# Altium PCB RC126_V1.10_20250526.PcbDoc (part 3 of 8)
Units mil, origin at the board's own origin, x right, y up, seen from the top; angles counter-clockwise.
Board outline 6299.62 x 3544.12 mil, 4 copper layers (Top, GND, Power, Bottom), stack 35.4 mil thick; 509 components, 417 nets, 1867 pads, 2150 vias.
Unrouted connection lines stored in the file: 1451.
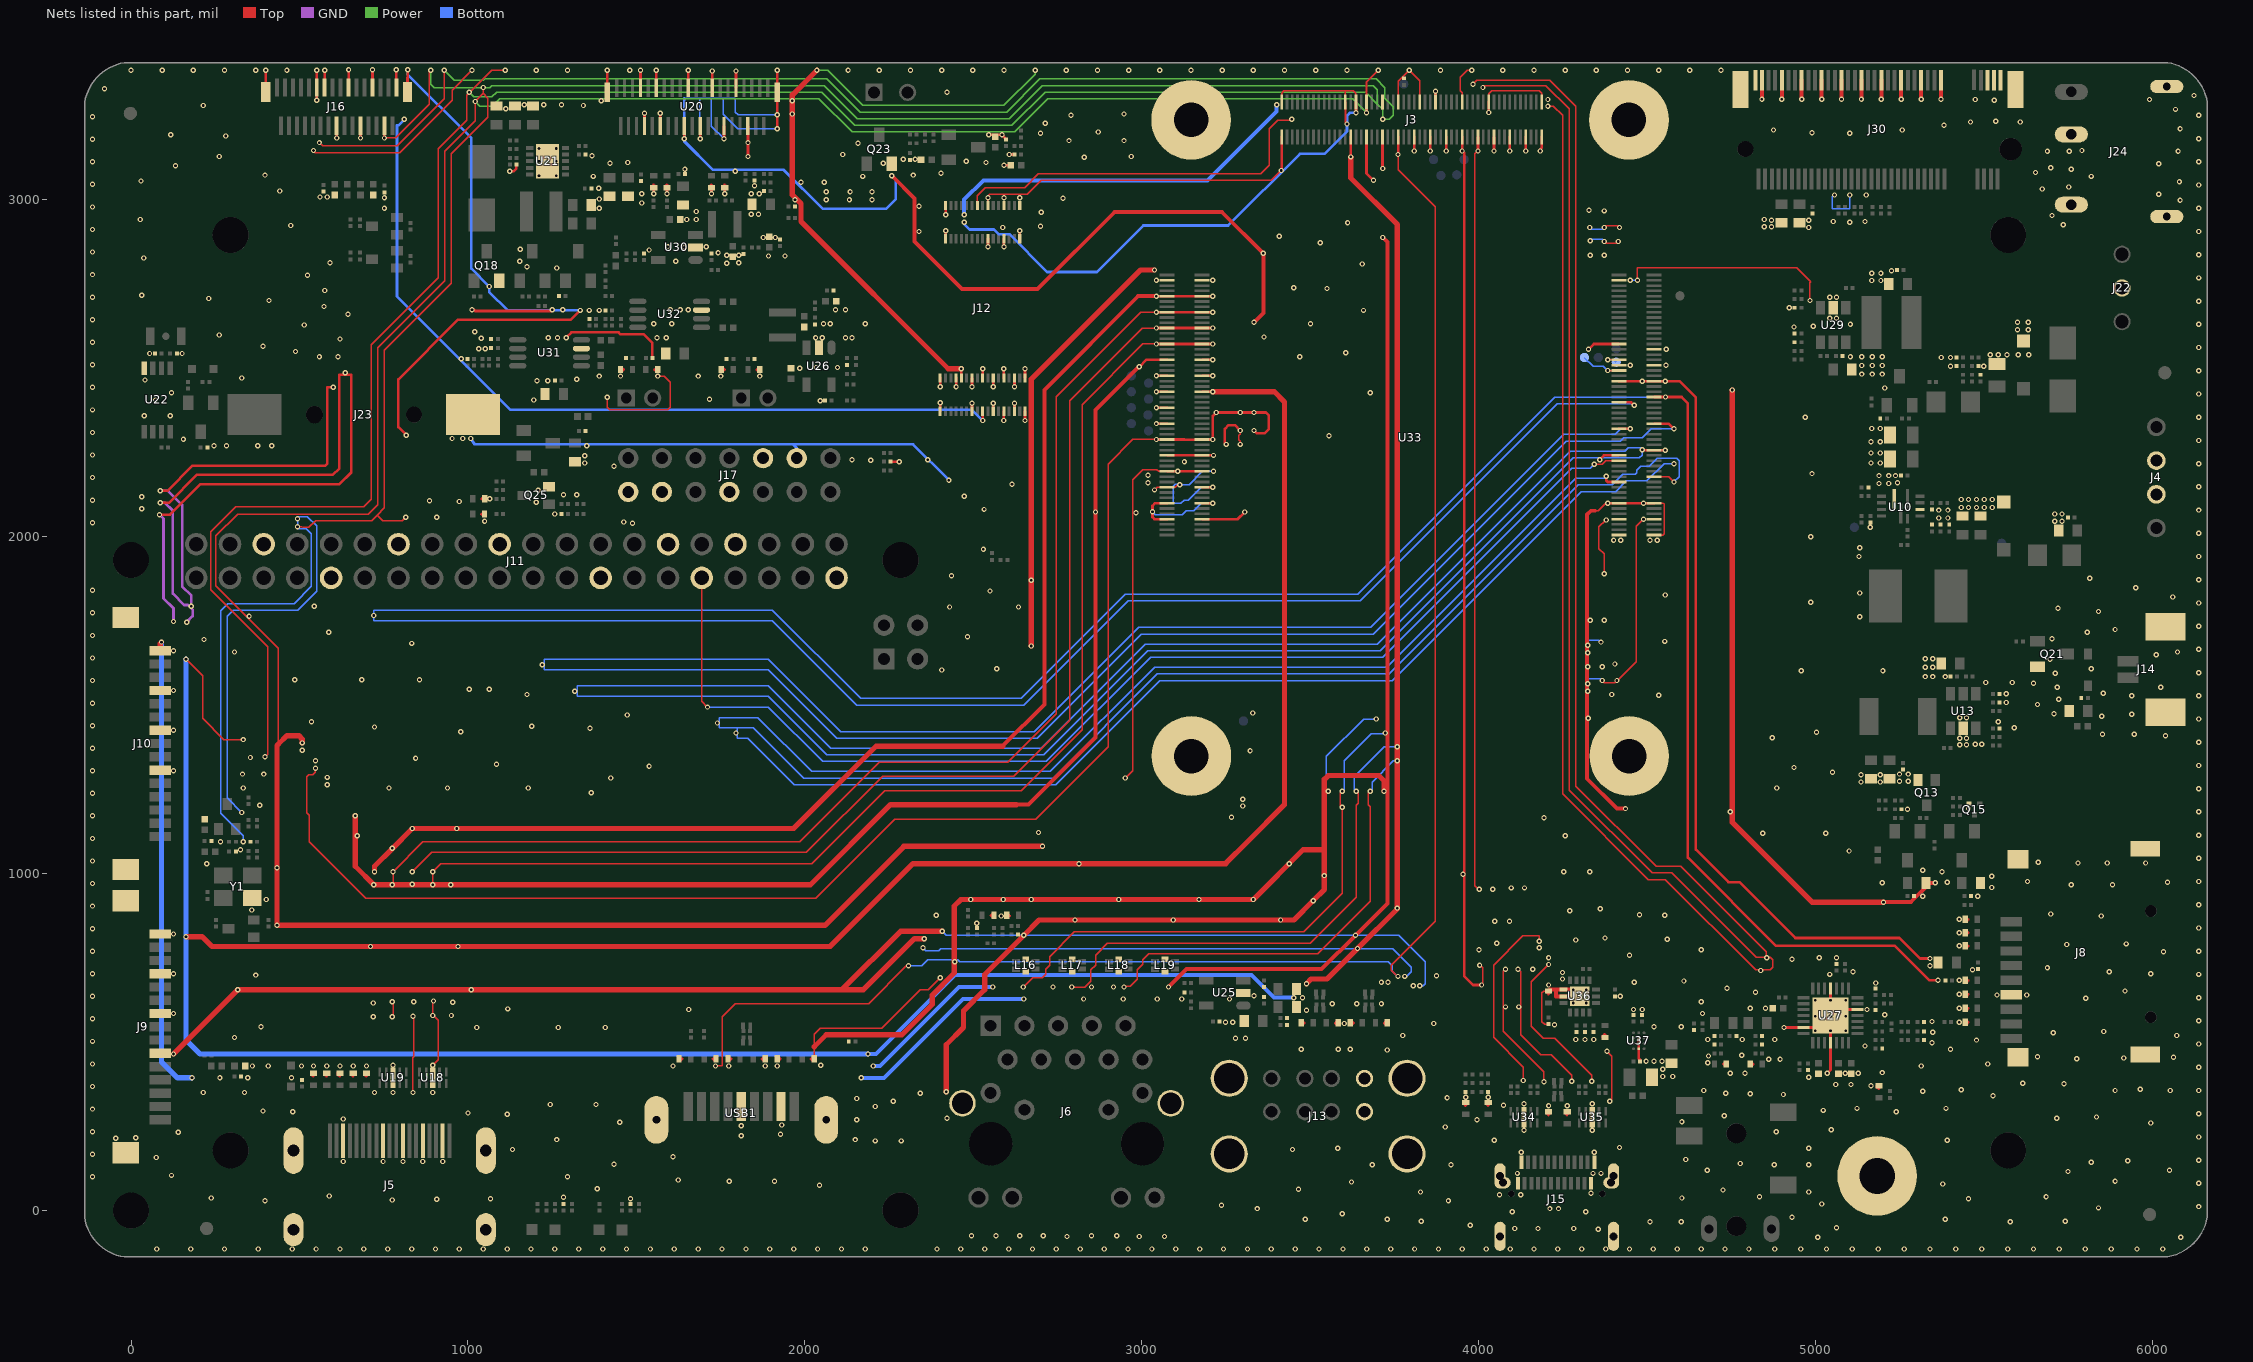
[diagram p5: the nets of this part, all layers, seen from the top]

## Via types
v1: diameter 15.75, hole 7.87, Top to Bottom, 2047 vias
v2: diameter 19.68, hole 11.81, Top to Bottom, 103 vias

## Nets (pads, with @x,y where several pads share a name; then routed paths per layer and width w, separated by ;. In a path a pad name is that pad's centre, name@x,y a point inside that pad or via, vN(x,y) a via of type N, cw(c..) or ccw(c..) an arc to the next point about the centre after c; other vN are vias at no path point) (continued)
GND: C1.2 C78.2 C79.2 C83.2 C84.2 C89.2 C90.2 C106.2 C107.2 C144.2 C146.2 C148.2 C150.2 C151.2 C153.2 C154.2 C156.2 C157.2 C158.2 C159.2 C161.1 C162.2 C163.2 C164.2 C167.2 C168.2 C169.1 C170.2 C171.2 C172.2 C174.2 C175.2 C176.2 C177.2 C178.2 C179.2 C180.1 C182.2 C183.2 C184.2 C185.2 C186.2 C187.1 C188.2 C189.1 C190.2 C191.2 C192.2 C193.2 C194.2 C195.2 C196.2 C197.2 C198.2 C199.2 C200.2 C202.2 C203.2 C206.2 C207.2 C208.2 C209.2 C211.2 C212.2 C213.2 C214.2 C215.2 C216.2 C218.2 C219.2 C220.2 C223.2 C224.2 C225.2 C226.2 C227.2 C229.2 C230.2 C231.2 C232.2 C233.2 C234.2 C235.2 C236.2 C237.2 C238.2 C239.2 C240.2 C241.2 C243.2 C244.2 C245.2 C246.2 C255.2 C256.2 C257.2 C258.2 C269.2 C270.2 C271.2 C272.2 C273.2 C274.2 C277.2 C279.2 C280.2 C281.2 C282.2 C283.1 C284.1 C285.2 C287.2 C288.2 C290.1 C291.1 C292.2 C294.2 C295.2 C297.2 C298.2 D1.1 D2.2 D3.2 D5.1 D7.2 D9.2 D10.2 D11.2 D12.2 D14.2 D15.2 D16.2 D17.1 D18.1 D19.1 D20.1 D21.1 D22.1 D23.1 D25.2 D26.2 D27.2 D28.2 D31.2 D32.2 D33.1 D34.1 D35.1 D36.1 D37.1 D38.1 D39.1 D40.1 D41.1 D42.1 D43.1 D44.1 D45.1 D46.1 D47.1 D48.1 D49.1 D50.1 D51.1 D52.1 HOLE2.1 J3.1 J3.2 J3.8 J3.14 J3.20 J3.21 J3.26 J3.31 J3.32 J3.38 J3.41 J3.44 J3.47 J3.50 J3.55 J3.56 J3.61 J3.62 J3.67 J3.68 J3.71 J3.74 J3.75 J3.99 J3.100 J4.2 J4.3 J5.2 J5.5 J5.8 J5.11 J5.17 J5.20 J5.21 J5.22 J5.23 J6.19 J6.20 J8.6 J8.10 J8.11 J8.12 J8.13 J9.6 J9.9 J9.12 J9.15 J9.16 J9.17 J10.6 J10.9 J10.12 J10.15 J10.16 J10.17 J11.6 J11.9 J11.14 J11.20 J11.25 J11.30 J11.34 J11.39 J12.1 J12.3 J12.5 J12.7 J12.9 J12.11 J12.13 J12.14 J12.17 J12.18 J12.24 J12.26 J12.28 J12.30 J12.32 J12.34 J12.35 J12.38 J12.41 J12.43 J12.49 J12.50 J12.58 J12.61 J12.64 J13.4 J13.8 J13.9 J13.10 J13.11 J13.12 J14.3 J14.4 J15.A1 J15.A12 J15.B1 J15.B12 J15.E1 J15.E2 J15.E3 J15.E4 J15.E5 J15.E6 J16.1 J16.4 J16.7 J16.10 J16.13 J16.16 J16.19 J16.21 J16.32 J16.33 J17.1 J17.3 J17.7 J17.10 J17.12 J22.2 J23.2 J24.2 J24.3 J24.4 J24.5 J30.1 J30.3 J30.9 J30.15 J30.21 J30.27 J30.33 J30.39 J30.45 J30.51 J30.57 J30.71 J30.73 J30.75 J30.G1 J30.G2 L16.5 L16.6 L17.5 L17.6 L18.5 L18.6 L19.5 L19.6 Q13.2 Q15.2 Q18.2 Q21.2 Q23.2 Q25.2 R4.2 R6.1 R27.1 R72.2 R177.1 R179.1 R201.1 R202.2 R205.2 R210.2 R217.2 R223.2 R226.2 R236.1 R239.1 R243.1 R244.2 R245.2 R251.2 R253.2 R280.2 R281.2 R286.1 R290.2 R298.1 R315.2 R316.2 R317.2 R318.2 R319.2 R330.2 R332.2 R333.2 R340.2 R341.2 R353.2 R354.2 R355.2 R359.2 U10.2 U10.10 U13.2 U18.3 U18.8 U19.3 U19.8 U20.6 U20.9 U20.12 U20.15 U20.18 U20.21 U20.22 U20.28 U20.29 U20.32 U20.33 U20.40 U20.41 U21.11 U22.4 U25.2 U26.2 U27.4 U27.13 U27.18 U27.26 U27.29 U29.2 U30.2 U31.7 U32.7 U33.1 U33.2 U33.7 U33.8 U33.13 U33.14 U33.22 U33.23 U33.32 U33.33 U33.42 U33.43 U33.52 U33.53 U33.59 U33.60 U33.65 U33.66 U33.71 U33.74 U33.98 U33.107 U33.108 U33.113 U33.114 U33.119 U33.120 U33.125 U33.126 U33.131 U33.132 U33.137 U33.138 U33.144 U33.150 U33.155 U33.156 U33.161 U33.162 U33.167 U33.168 U33.173 U33.174 U33.179 U33.180 U33.185 U33.186 U33.191 U33.192 U33.197 U33.198 U33.201 U33.202 U33.203 U33.204 U34.3 U34.8 U35.3 U35.8 U36.8 U36.9 U36.15 U37.A2 U37.B2 U37.C2 USB1.4 USB1.7 USB1.10 USB1.11 Y1.2 | length 175701.2
  Top w3.94: v1(163.39,1635.83) 212.6,1586.61 212.6,1460.63 275.59,1397.64 v1(332.68,1397.64) ; v1(397.64,1346.46) 405.51,1354.33 405.51,1673.23 236.22,1842.52 236.22,2013.78 311.02,2088.58 690.94,2088.58 712.6,2110.24 712.6,2568.9 911.42,2767.72 911.42,3151.57 996.06,3236.22 996.06,3309.06 1070.87,3383.86 v1(1110.24,3383.86) ; 437.01,1383.86 437.01,1669.29 251.97,1854.33 251.97,2001.97 316.93,2066.93 704.05,2066.93 732.28,2095.16 732.28,2561.02 931.1,2759.84 931.1,3143.7 1021.65,3234.25 v1(1021.65,3291.34) 1045.28,3314.96 ; v1(494.09,2029.53) 506.99,2029.53 508.96,2027.56 527.99,2027.56 547.68,2047.24 713.89,2047.24 730.64,2063.99 ; v1(541.34,3145.67) 547.24,3139.76 797.24,3139.76 952.76,3295.28 952.76,3324.8 v1(1011.81,3383.86) ; v1(547.24,1312.99) 547.24,1301.18 539.37,1293.31 527.56,1293.31 521.65,1287.4 521.65,1181.1 529.53,1173.23 529.53,1094.49 696.85,927.17 2031.5,927.17 2265.75,1161.42 2685.04,1161.42 2899.61,1375.98 2899.61,2214.57 2973.23,2288.19 v1(3042.91,2288.19) v1@3043.31,2288.19 ; v1(559.06,3169.29) 568.9,3159.45 789.37,3159.45 929.13,3299.21 v1(929.13,3383.86) ; v1(751.97,3183.07) 785.43,3183.07 884.84,3282.48 884.84,3383.86 v1(889.76,3383.86) ; v1(775.59,574.8) 777.56,576.77 777.56,618.11 v1(775.59,620.08) ; v1@777.56,966.54 v1(777.56,1005.91) 866.14,1094.49 1984.25,1094.49 2220.47,1330.71 2602.36,1330.71 2746.06,1474.41 2746.06,2415.35 2996.85,2666.14 v1(3042.91,2666.14) ; v1(814.96,2057.09) 805.12,2047.24 747.38,2047.24 730.64,2063.99 ; v1(834.65,1005.91) 891.73,1062.99 2003.94,1062.99 2230.32,1289.37 2620.08,1289.37 2785.43,1454.72 2785.43,2403.54 3000.79,2618.9 v1(3042.91,2618.9) ; v1(836.61,350.39) 836.61,454.72 838.58,454.72 838.58,574.8 v1(836.61,576.77) ; v1(895.67,431.1) 911.42,446.85 911.42,564.96 895.67,580.71 895.67,622.05 v1(897.64,622.05) ; v1(895.67,966.54) v1(895.67,1005.91) 919.29,1029.53 2019.68,1029.53 2236.22,1246.06 2641.73,1246.06 2822.83,1427.17 2822.83,2391.73 3002.76,2571.65 v1(3042.91,2571.65) ; v1(1045.28,3332.68) 1045.28,3314.96 ; v1(1413.39,2413.39) 1413.39,2383.86 1421.26,2375.98 1592.52,2375.98 1600.39,2383.86 1600.39,2458.66 1582.68,2476.38 v1(1562.99,2476.38) ; v1(1734.25,429.13) 1753.94,429.13 1753.94,574.8 1793.31,614.17 2188.98,614.17 2301.18,726.38 v1(2307.09,726.38) ; D40.1@2027.56,450.79 2027.56,486.22 2027.56,523.62 2045.28,541.34 2228.35,541.34 2342.52,655.51 2366.14,655.51 v1(2401.57,690.94) ; J12.43@2511.42,2982.28 2511.42,3011.81 2535.04,3035.43 2651.57,3035.43 2692.91,3076.77 3352.36,3076.77 3377.95,3102.36 3377.95,3210.63 3403.54,3236.22 3442.91,3236.22 3448.82,3236.22 v1(3444.88,3238.19) ; J12.41@2542.91,2982.28 2542.91,3009.84 2548.82,3015.75 2659.45,3015.75 2700.79,3057.09 3383.86,3057.09 v1(3413.39,3086.61) ; v1(2647.64,663.39) 2675.2,690.94 2704.72,690.94 2714.57,700.79 2714.57,716.54 2726.38,728.35 2726.38,753.94 2799.21,826.77 3480.32,826.77 3594.49,940.94 v1(3594.49,1196.85) 3588.58,1202.76 3588.58,1238.19 v1(3594.49,1244.09) ; v1(2791.34,663.39) 2830.71,663.39 2848.43,681.1 2848.43,714.57 2862.2,728.35 2862.2,757.87 2897.64,793.31 3500,793.31 3635.83,929.13 3635.83,1202.76 3641.73,1208.66 3641.73,1238.19 v1(3635.83,1244.09) ; v1(2946.85,663.39) 2948.82,665.35 2964.57,665.35 2986.22,687.01 2986.22,714.57 3001.97,730.32 3001.97,744.09 3019.68,761.81 3521.65,761.81 3677.17,917.32 3677.17,1198.82 3671.26,1204.72 3671.26,1238.19 v1(3677.17,1244.09) ; v1(2950.79,1283.46) 2972.44,1305.12 2972.44,2169.29 3001.97,2198.82 3044.09,2198.82 3049.21,2193.7 U33.126@3074.8,2193.7 ; v1(3037.4,2138.58) 3045.28,2146.46 U33.120@3074.8,2146.46 3098.43,2146.46 3106.3,2154.33 v1(3112.2,2154.33) ; v1@3208.27,2099.21 v1(3210.24,2099.21) ; v1(3291.34,2273.62) 3291.34,2283.46 3287.4,2287.4 3287.4,2300.1 3291.34,2304.03 v1(3291.34,2314.96) ; J3.100@3414.57,3181.9 J3.100@3414.57,3185.83 ; J3.99@3414.57,3289.77 3414.57,3302 3414.57,3316.14 3421.26,3322.83 3603.54,3322.83 ; J3.75@3603.55,3289 J3.75@3603.55,3289.77 3603.54,3322.83 ; J3.74@3619.3,3178.4 J3.74@3619.3,3185.83 ; J3.71@3635.04,3288.2 J3.71@3635.04,3289.77 3635.04,3314.96 3627.17,3322.83 3603.54,3322.83 ; J3.68@3666.54,3176.6 J3.68@3666.54,3185.83 ; J3.67@3666.54,3289.2 J3.67@3666.54,3289.77 ; J3.62@3713.78,3179.6 J3.62@3713.78,3185.83 ; v1(3759.84,694.88) 3757.87,694.88 3740.16,712.6 3740.16,728.35 3870.08,858.27 3870.08,2978.35 3759.84,3088.58 v1(3759.84,3133.86) ; J3.55@3761.02,3290.3 3761.02,3351.57 v1(3793.31,3383.86) 3824.02,3353.15 3824.02,3304.6 J3.47@3824.02,3289.77 ; J3.56@3761.03,3182.4 J3.56@3761.03,3185.83 ; J3.55@3761.03,3289.77 J3.55@3761.03,3290.3 ; J3.50@3808.27,3179.3 J3.50@3808.27,3185.83 ; J3.44@3855.52,3179.8 J3.44@3855.52,3185.83 ; J3.41@3871.26,3289.77 J3.41@3871.26,3299 ; J3.38@3902.76,3178.1 J3.38@3902.76,3185.83 ; J3.32@3950,3178.6 J3.32@3950,3185.83 ; v1(3978.35,3383.86) 3964.96,3383.86 3944.09,3362.99 3944.09,3323.62 3950,3317.72 J3.31@3950,3299.8 ; v1(3982.28,3342.52) 3994.09,3354.33 4210.63,3354.33 4287.4,3277.56 4287.4,1259.84 4525.59,1021.65 4598.43,1021.65 4852.36,767.72 v1@4852.36,751.97 ; v1(3997.24,3144.49) 3988.19,3135.43 3988.19,964.57 3998.03,954.72 4000,954.72 v1(4001.18,953.54) ; J3.26@3997.25,3179.3 J3.26@3997.25,3185.83 ; v1(4001.97,728.35) 4003.94,728.35 4011.81,720.47 4011.81,673.23 v1(4007.87,669.29) ; v1(4011.81,3332.68) 4017.72,3338.58 4198.82,3338.58 4267.72,3269.69 4267.72,1248.03 4513.78,1001.97 4572.83,1001.97 4822.83,751.97 v1@4852.36,751.97 ; J3.21@4028.74,3279.6 J3.21@4028.74,3289.77 4028.74,3314.17 4037.4,3322.83 4179.13,3322.83 4186.22,3315.75 4186.22,3298.5 J3.1@4186.22,3289.77 ; J3.20@4044.49,3178 J3.20@4044.49,3185.83 ; v1(4078.74,716.54) 4072.83,710.63 4072.83,531.5 4192.91,411.42 v1(4192.91,381.89) ; J3.14@4091.74,3179.6 J3.14@4091.74,3185.83 ; v1(4116.14,716.54) 4124.02,708.66 4124.02,521.65 4183.07,462.6 4214.57,462.6 4275.59,401.57 v1(4275.59,383.86) ; v1(4131.89,385.83) 4131.89,425.2 4043.31,513.78 4043.31,728.35 4129.92,814.96 4179.13,814.96 v1(4179.13,799.21) ; J3.8@4138.98,3176.9 J3.8@4138.98,3185.83 ; v1(4204.72,3277.56) 4220.47,3277.56 4248.03,3250 4248.03,1236.22 4501.97,982.28 4553.15,982.28 4820.87,714.57 4864.17,714.57 4872.05,722.44 4872.05,744.09 4864.17,751.97 v1@4852.36,751.97 ; C257.2@4206.69,553.15 4194.88,553.15 4187.01,561.02 4187.01,645.67 4192.91,651.57 D47.1@4206.69,651.57 ; v1(4206.69,730.32) 4155.51,679.13 4155.51,547.24 4190.94,511.81 4224.41,511.81 4334.65,401.57 v1(4334.65,383.86) ; 4344.49,2076.77 4354.33,2076.77 4376.77,2099.21 v1(4381.89,2099.21) ; v1(4366.14,1572.83) 4372.05,1566.93 4403.54,1566.93 v1(4409.45,1572.83) 4411.42,1574.8 4413.39,1574.8 4466.54,1627.95 4466.54,2030.32 v1(4488.19,2051.97) ; v1(4372.05,1889.76) 4372.05,1948.82 4356.3,1964.57 4356.3,2029.53 4375.98,2049.21 v1(4377.95,2049.21) ; v1(4372.05,2875.98) 4377.95,2870.08 4407.48,2870.08 v1(4413.39,2875.98) ; v1(4372.05,2917.32) 4377.95,2923.23 4411.42,2923.23 v1(4417.32,2917.32) ; v1(4379.92,472.44) 4393.7,458.66 4393.7,330.71 v1(4387.8,324.8) ; v1(4470.47,2760.63) 4470.47,2797.24 4942.91,2797.24 4984.25,2755.91 4982.28,2753.94 v1(4982.28,2700.79) ; U33.1@4520.08,2004.72 4546.06,2004.72 4549.21,2007.87 4549.21,2097.24 4547.24,2099.21 U33.13@4520.08,2099.21 ; U33.23@4520.08,2177.95 4562.99,2177.95 v1(4578.74,2162.2) ; v1(4854.33,750) v1@4852.36,751.97 ; 730.64,2063.99 751.97,2085.32 751.97,2553.15 950.79,2751.97 950.79,3135.83 1059.06,3244.09 1059.06,3301.18 1045.28,3314.96 ; J3.31@3950,3299.8 J3.31@3950,3289.77 J3.31@3950,3299.8
  Top w5.91: J3.75@3603.55,3289.77 3603.54,3289 3603.54,3229.13 v1(3608.27,3224.41) ; J3.67@3666.54,3289.77 3666.54,3349.61 v1(3700.79,3383.86)
  Top w7.87: v1(84.65,2064.96) 116.14,2064.96 206.69,2155.51 618.11,2155.51 653.54,2190.94 653.54,2480.32 618.11,2480.32 618.11,2202.76 598.43,2183.07 194.88,2183.07 112.2,2100.39 v1(86.61,2100.39) ; v1(86.61,2135.83) 108.27,2135.83 183.07,2210.63 576.77,2210.63 582.68,2216.54 582.68,2442.91 v1(600.39,2442.91) ; v1(399.61,3383.86) 399.61,3362.7 400,3362.31 J16.32@400,3319.5 ; v1(551.18,3295.28) 551.18,3311.58 J16.21@551.18,3332.68 551.18,3368.11 v1(551.18,3383.86) ; J16.19@574.8,3332.68 574.8,3368.11 v1(574.8,3383.86) ; v1(610.24,3183.07) J16.16@610.23,3219.5 ; J16.13@645.67,3332.68 645.67,3368.11 v1(645.67,3385.83) ; v1(681.1,3183.07) 681.1,3198.4 J16.10@681.1,3219.5 ; J16.7@716.53,3332.68 716.53,3368.11 v1(716.54,3385.83) ; v1(751.97,3183.07) J16.4@751.97,3219.5 ; J16.1@787.4,3332.68 v1(787.4,3385.83) ; v1(816.93,2301.18) 793.31,2324.8 793.31,2466.54 970.47,2643.7 1305.12,2643.7 v1(1332.68,2671.26) ; J16.33@820.47,3319.5 820.47,3362.31 820.87,3362.7 v1(820.87,3385.83) ; v1(1011.81,2673.23) 1017.72,2673.23 1021.65,2669.29 1246.06,2669.29 v1(1250,2673.23) ; v1(1124.02,3084.65) 1135.83,3084.65 1143.7,3092.52 C180.1@1143.7,3104.33 ; v1(1291.34,2590.55) 1307.09,2606.3 1446.85,2606.3 1452.76,2600.39 1521.65,2600.39 1547.24,2574.8 C288.2@1547.24,2529.53 ; U20.40@1413.39,3318.71 v1(1413.39,3383.86) ; U20.33@1511.81,3331.89 v1(1511.81,3383.86) ; U20.32@1523.62,3218.71 v1(1523.62,3255.91) ; v1(1551.18,3017.72) D26.2@1551.18,3035.43 ; U20.29@1559.06,3331.89 v1(1559.06,3383.86) ; U20.28@1570.87,3218.71 v1(1570.87,3255.91) ; v1(1590.55,3017.72) D27.2@1590.55,3035.43 ; v1(1641.73,3181.1) U20.22@1641.73,3218.71 ; U20.21@1653.54,3331.89 v1(1653.54,3383.86) ; v1(1688.98,3181.1) U20.18@1688.98,3218.71 ; v1(1722.44,3017.72) D25.2@1722.44,3035.43 ; U20.15@1724.41,3331.89 v1(1724.41,3381.89) ; v1(1759.84,3181.1) U20.12@1759.84,3218.71 ; v1(1761.81,3017.72) D28.2@1761.81,3035.43 ; U20.9@1795.28,3331.89 v1(1795.28,3381.89) ; v1(1830.71,3127.95) v1(1830.71,3169.29) U20.6@1830.71,3218.71 ; v1(1917.32,3210.63) v1(1917.32,3251.97) U20.41@1917.32,3318.71 v1(1917.32,3383.86) ; R223.2@2253.94,2222.44 v1(2279.53,2222.44) ; J12.18@2401.18,2372.05 v1(2401.18,2397.64) ; v1(2401.18,2444.88) J12.17@2401.18,2470.47 ; J12.50@2416.93,2883.86 2417.32,2883.86 v1(2417.32,2907.48) ; J12.49@2416.93,2982.28 2417.32,2982.28 v1(2417.32,2954.72) ; v1(2448.43,2444.88) J12.14@2448.43,2470.47 ; J12.13@2464.17,2470.47 v1(2464.17,2498.03) ; J12.24@2495.67,2372.05 v1(2495.67,2395.67) ; v1(2495.67,2444.88) J12.11@2495.67,2470.47 ; v1(2527.17,2344.49) J12.26@2527.17,2372.05 ; J12.9@2527.17,2470.47 v1(2527.17,2498.03) ; J12.58@2542.91,2883.86 2542.91,2860.63 v1(2543.31,2860.24) ; v1(2545.28,3192.91) C209.2@2564.96,3192.91 ; J12.28@2558.66,2372.05 v1(2558.66,2395.67) ; v1(2558.66,2444.88) J12.7@2558.66,2470.47 ; C209.2@2564.96,3187.01 C209.2@2564.96,3192.91 ; v1(2590.16,2344.49) J12.30@2590.16,2372.05 ; J12.5@2590.16,2470.47 v1(2590.16,2498.03) ; J12.61@2590.16,2883.86 2590.16,2860.63 v1(2590.55,2860.24) ; v1(2590.55,3102.36) C229.2@2610.24,3102.36 ; C226.2@2596.46,3179.13 2594.49,3179.13 2594.49,3181.1 v1(2584.65,3192.91) C209.2@2564.96,3192.91 ; v1(2606.3,3133.86) C230.2@2622.05,3133.86 ; J12.32@2621.65,2372.05 v1(2621.65,2395.67) ; v1(2621.65,2444.88) J12.3@2621.65,2470.47 ; J12.64@2637.4,2883.86 2637.4,2907.09 v1(2637.8,2907.48) ; v1(2653.15,2344.49) J12.34@2653.15,2372.05 ; J12.1@2653.15,2470.47 v1(2653.15,2498.03) ; v1(2992.13,2503.94) 3012.6,2524.41 U33.168@3074.8,2524.41 ; v1(3042.91,2335.43) U33.144@3074.8,2335.43 ; v1(3042.91,2382.68) U33.150@3074.8,2382.68 ; v1(3042.91,2429.92) U33.156@3074.8,2429.92 ; v1(3042.91,2477.17) U33.162@3074.8,2477.17 ; v1(3042.91,2571.65) v1(3210.24,2571.65) ; v1(3042.91,2666.14) v1(3210.24,2666.14) ; v1(3042.91,2713.39) v1(3210.24,2713.39) ; v1@3043.31,2288.19 3126.19,2288.19 3126.98,2287.4 3162.31,2287.4 3163.1,2288.19 U33.137@3178.74,2288.19 v1(3210.24,2288.19) 3210.24,2357.87 v1(3220.47,2368.11) v1(3291.34,2368.11) v1(3332.68,2368.11) 3368.11,2368.11 3375.98,2360.24 3375.98,2318.28 3364.79,2307.09 3340.55,2307.09 v1(3332.68,2314.96) ; U33.108@3074.8,2051.97 3037.01,2051.97 3031.1,2057.87 3031.1,2091.34 3038.98,2099.21 U33.114@3074.8,2099.21 ; U33.126@3074.8,2193.7 U33.125@3178.74,2193.7 ; U33.132@3074.8,2240.94 v1(3212.2,2240.94) ; U33.107@3178.74,2051.97 3284.25,2051.97 v1(3305.12,2072.83) ; U33.113@3178.74,2099.21 v1@3208.27,2099.21 ; U33.119@3178.74,2146.46 v1(3210.24,2146.46) ; U33.155@3178.74,2429.92 v1(3210.24,2429.92) ; U33.161@3178.74,2477.17 v1(3210.24,2477.17) ; U33.167@3178.74,2524.41 v1(3210.24,2524.41) ; v1(3250,2273.62) 3246.06,2277.56 3246.06,2319.52 3257.26,2330.71 3275.59,2330.71 v1(3291.34,2314.96) ; v1(3413.39,3086.61) 3414.57,3087.8 3414.57,3181.9 J3.100@3414.57,3185.83 ; v1@3442.91,3236.22 v1(3444.88,3238.19) ; v1(3619.29,3126.77) 3619.29,3178.4 J3.74@3619.3,3185.83 ; v1(3635.04,3258.27) 3635.04,3288.2 J3.71@3635.04,3289.77 ; J3.68@3666.54,3185.83 3666.54,3176.6 3666.54,3077.56 v1(3687.01,3057.09) ; v1(3666.54,3258.27) 3666.54,3289.2 J3.67@3666.54,3289.77 ; J3.62@3713.78,3185.83 3713.78,3179.6 3713.78,3093.31 v1(3714.57,3092.52) ; v1(3759.84,3133.86) 3761.02,3135.04 3761.02,3182.4 J3.56@3761.03,3185.83 ; v1(3808.27,3144.49) 3808.27,3179.3 J3.50@3808.27,3185.83 ; v1(3855.51,3144.49) 3855.51,3179.8 J3.44@3855.52,3185.83 ; J3.41@3871.26,3289.77 3871.26,3299 v1(3871.26,3321.65) ; v1(3902.76,3144.49) 3902.76,3178.1 J3.38@3902.76,3185.83 ; J3.32@3950,3185.83 3950,3178.6 v1(3950,3144.49) 3956.69,3137.8 3956.69,694.88 3982.28,669.29 v1(4007.87,669.29) ; v1(3997.24,3144.49) 3997.24,3179.3 J3.26@3997.25,3185.83 ; v1(4028.74,3258.66) 4028.74,3279.6 J3.21@4028.74,3289.77 ; v1(4044.49,3144.49) 4044.49,3178 J3.20@4044.49,3185.83 ; v1(4091.73,3144.49) 4091.73,3179.6 J3.14@4091.74,3185.83 ; v1(4138.98,3144.49) 4138.98,3176.9 J3.8@4138.98,3185.83 ; v1(4182.28,3144.49) 4182.28,3149.61 4186.22,3153.54 J3.2@4186.22,3185.83 ; v1(4325.2,2555.91) 4340.94,2571.65 U33.74@4415.35,2571.65 ; v1(4358.27,2228.35) 4370.87,2240.94 U33.32@4415.35,2240.94 ; v1(4377.95,2179.13) 4377.95,2166.14 4381.89,2162.2 U33.22@4415.35,2162.2 ; v1(4381.89,2099.21) U33.13@4520.08,2099.21 ; U33.42@4415.35,2319.69 v1(4448.82,2319.69) ; U33.52@4415.35,2398.43 4451.97,2398.43 v1(4460.63,2389.76) ; U33.60@4415.35,2461.42 4531.5,2461.42 U33.59@4520.08,2461.42 v1(4553.15,2461.42) 4594.49,2461.42 4643.7,2412.2 4643.7,1070.87 4740.16,974.41 4773.62,974.41 4938.98,809.06 5248.03,809.06 5309.06,748.03 v1(5338.58,748.03) ; U37.C2@4474.41,511.81 4474.41,450.79 4478.35,446.85 R353.2@4478.35,442.91 ; v1(4484.25,2257.87) 4485.43,2256.69 U33.33@4520.08,2256.69 v1(4553.15,2256.69) ; U33.43@4520.08,2335.43 4562.99,2335.43 v1(4578.74,2319.69) ; U33.53@4520.08,2414.17 4601.57,2414.17 4620.08,2395.67 4620.08,1047.24 4881.89,785.43 5234.25,785.43 5336.61,683.07 v1(5362.2,683.07) ; v1(4905.51,543.31) U27.13@4962.6,543.31 ; v1(5033.46,407.48) 5043.31,417.32 U27.18@5043.31,498.03 ; v1(3042.91,2618.9) v1(3210.24,2618.9) U33.179@3178.74,2618.9 U33.180@3074.8,2618.9 v1(3042.91,2618.9)
  Top w9.84: U27.13@4962.6,543.31 5043.31,543.31 v1(5043.31,576.77) U27.29@5043.31,578.74 ; U27.18@5043.31,498.03 U27.29@5043.31,578.74 ; U27.4@5043.31,659.45 5043.31,635.83 ; U27.26@5124.02,596.46 5043.31,596.46 5043.31,635.83 ; U27.29@5043.31,578.74 5043.31,635.83
  Top w11.81: v1(2257.87,3070.87) 2324.8,3003.94 2324.8,2875.98 2466.54,2734.25 2689.55,2734.25 2917.9,2962.6 3238.19,2962.6 v1(3360.24,2840.55) 3360.24,2663.39 v1(3332.68,2635.83) ; 2586.61,1377.95 2710.63,1501.97 2710.63,2435.04 2988.98,2713.39 v1(3042.91,2713.39) ; 2627.95,1204.72 2663.39,1204.72 2862.2,1403.54 v1(2862.2,2072.83) 2862.2,2375.98 2990.16,2503.94 v1(2992.13,2503.94) ; v1(3078.74,663.39) 3131.89,716.54 3533.46,716.54 v1(3633.86,816.93) 3728.35,911.42 3728.35,2874.02 v1(3714.57,2887.8) ; D47.1@4206.69,651.57 4210.63,655.51 4228.35,655.51 ; v1(4279.53,616.14) 4279.53,635.83 U36.9@4251.57,635.83 4228.35,635.83 4228.35,655.51 ; v1(4318.9,655.51) U36.8@4251.57,655.51 4228.35,655.51 ; 4344.49,2076.77 4332.68,2076.77 4320.87,2064.96 4320.87,1281.5 4409.45,1192.91 v1(4435.04,1192.91) ; v1(4839.76,3297.44) J30.3@4839.76,3354.53 ; v1(4898.82,3297.44) J30.9@4898.82,3354.53 ; v1(4957.87,3297.44) J30.15@4957.87,3354.53 ; v1(5016.93,3297.44) J30.21@5016.93,3354.53 ; v1(5075.98,3297.44) J30.27@5075.98,3354.53 ; v1(5135.04,3297.44) J30.33@5135.04,3354.53 ; v1(5194.09,3297.44) J30.39@5194.1,3354.53 ; v1(5200.79,915.35) 5281.5,915.35 5338.58,972.44 v1(5354.33,972.44) ; v1(5253.15,3297.44) J30.45@5253.15,3354.53 ; v1(5312.2,3297.44) J30.51@5312.21,3354.53 ; v1(5371.26,3297.44) J30.57@5371.26,3354.53
  Top w15.75: J10.15@86.61,1661.42 86.61,1683.07 v1(90.55,1687.01) ; v1(125.98,464.57) v1(316.93,655.51) v1(1009.84,655.51) 2110.24,655.51 ; v1(163.39,812.99) 210.63,812.99 240.16,783.46 v1(710.63,783.46) v1(970.47,783.46) 2074.8,783.46 2320.87,1029.53 v1(2812.99,1029.53) 3248.34,1029.53 3313.3,1094.49 3423.23,1204.72 3423.23,2399.61 3392.91,2429.92 v1(3210.24,2429.92) ; v1(507.87,1387.8) 507.87,1399.61 498.03,1409.45 462.6,1409.45 437.01,1383.86 433.07,1379.92 v1(433.07,846.46) 2059.06,846.46 2293.31,1080.71 v1(2704.72,1080.71) ; v1(665.35,1171.26) 665.35,1021.65 v1(720.47,966.54) v1(775.59,966.54) 777.56,966.54 v1(895.67,966.54) v1(948.82,966.54) 2015.75,966.54 2253.94,1204.72 2627.95,1204.72 ; v1(722.44,1005.91) 722.44,1021.65 v1(775.59,1074.8) v1(834.65,1133.86) 1966.54,1133.86 2210.63,1377.95 2586.61,1377.95 ; 2027.56,486.22 2062.99,521.65 2287.4,521.65 2377.95,612.2 2377.95,639.76 2442.91,704.72 2442.91,903.54 2462.6,923.23 v1(2492.13,923.23) v1(2588.58,923.23) v1(2671.26,923.23) v1(2931.1,923.23) v1(3169.29,923.23) v1(3330.71,923.23) 3478.35,1070.87 3541.34,1070.87 ; v1(2035.43,3383.86) 1962.6,3311.02 1962.6,3013.78 1988.19,2988.19 1988.19,2935.04 2425.2,2498.03 v1(2464.17,2498.03) ; v1(2354.33,807.09) 2324.8,807.09 2173.23,655.51 2110.24,655.51 ; v1(2407.48,828.74) 2283.46,828.74 2110.24,655.51 ; v1(2419.29,352.36) 2419.29,492.13 2470.47,543.31 2470.47,592.52 2533.46,655.51 2533.46,700.79 v1(2649.61,816.93) 2694.88,862.2 v1(2801.18,862.2) v1(3092.52,862.2) v1(3411.42,862.2) 3450.79,862.2 v1(3507.87,919.29) 3541.34,952.76 v1(3541.34,994.09) 3541.34,1070.87 ; v1(2671.26,1675.2) 2671.26,2466.54 2996.06,2791.34 v1(3037.4,2791.34) ; v1(3488.19,673.23) 3501.97,687.01 3549.21,687.01 v1(3639.76,777.56) 3757.87,895.67 v1(3757.87,897.64) v1(3757.87,1334.65) v1(3757.87,1375.98) 3757.87,2926.38 3619.29,3064.96 v1(3619.29,3126.77) ; v1(3718.5,1244.09) 3718.5,1275.59 3702.76,1291.34 3553.15,1291.34 3541.34,1279.53 3541.34,1070.87 ; v1(4751.97,2435.04) 4751.97,1151.57 4988.19,915.35 v1(5200.79,915.35)
  GND w7.87: v1(84.65,2064.96) 96.46,2053.15 96.46,1816.93 125.98,1787.4 v1(125.98,1748.03) ; v1(86.61,2100.39) 100.39,2100.39 124.02,2076.77 124.02,1830.71 157.48,1797.24 169.29,1797.24 183.07,1783.46 183.07,1763.78 v1(165.35,1746.06) ; v1(86.61,2135.83) 110.24,2135.83 151.57,2094.49 151.57,1852.36 179.13,1824.8 v1(179.13,1793.31)
  Power w3.94: v1(889.76,3383.86) 889.76,3342.52 899.61,3332.68 v1(1045.28,3332.68) 1064.96,3332.68 1070.87,3338.58 2057.09,3338.58 2155.51,3240.16 2606.3,3240.16 2704.72,3338.58 3687.01,3338.58 3698.82,3326.77 3698.82,3283.46 ; v1(929.13,3383.86) 958.66,3354.33 1045.28,3354.33 1049.21,3358.27 2064.96,3358.27 2163.39,3259.84 2598.43,3259.84 2696.85,3358.27 3694.88,3358.27 3720.47,3332.68 3720.47,3301.18 3746.06,3275.59 3746.06,3250 3734.25,3238.19 v1(3714.57,3238.19) 3714.57,3267.72 3698.82,3283.46 ; v1(1003.94,3318.9) 1017.72,3305.12 1070.87,3305.12 1084.65,3318.9 2049.21,3318.9 2147.64,3220.47 2614.17,3220.47 2712.6,3318.9 3663.39,3318.9 3698.82,3283.46 ; v1(1021.65,3291.34) 1035.43,3277.56 1072.83,3277.56 1094.49,3299.21 2041.34,3299.21 2139.76,3200.79 2622.05,3200.79 2720.47,3299.21 3625.59,3299.21 v1(3666.54,3258.27) ; v1(2035.43,3383.86) 2066.93,3383.86 2171.26,3279.53 2590.55,3279.53 2683.07,3372.05 v1(2683.07,3383.86)
  Bottom w3.94: v1(328.74,1181.1) 285.43,1224.41 285.43,1763.78 303.15,1781.5 494.09,1781.5 551.18,1838.58 551.18,2031.5 523.62,2059.06 494.09,2059.06 v1(494.09,2053.15) v1(494.09,2029.53) 494.09,2023.62 519.69,2023.62 535.43,2007.87 535.43,1852.36 484.25,1801.18 287.4,1801.18 265.75,1779.53 265.75,1179.13 332.68,1112.2 v1(332.68,1094.49) ; 1641.73,3301.18 1687.01,3301.18 ; v1(1688.98,3181.1) 1688.98,3224.51 1687.01,3226.48 1687.01,3301.18 ; v1(1759.84,3181.1) 1722.44,3218.5 1722.44,3301.18 ; v1(1917.32,3210.63) 1801.18,3210.63 1757.87,3253.94 1757.87,3301.18 ; v1(1917.32,3251.97) 1801.38,3251.97 1793.31,3260.04 1793.31,3301.18 1757.87,3301.18 ; v1(2307.09,726.38) 2346.46,726.38 2364.17,744.09 2452.76,744.09 2458.66,738.19 3730.32,738.19 3742.13,726.38 3742.13,710.63 3757.87,694.88 v1(3759.84,694.88) ; v1(2350.39,779.53) 2358.27,771.65 2397.64,771.65 2403.54,777.56 v1(3639.76,777.56) 3744.09,777.56 3799.21,722.44 3799.21,708.66 3785.43,694.88 v1(3779.53,694.88) ; v1(2407.48,828.74) 2419.29,816.93 v1(3633.86,816.93) 3761.81,816.93 3840.55,738.19 3840.55,673.23 3834.65,667.32 v1(3824.8,667.32) ; v1(3031.1,2073.62) 3039.76,2064.96 3120.08,2064.96 3131.89,2076.77 3153.54,2076.77 3175.98,2099.21 v1(3210.24,2099.21) ; v1(3210.24,2146.46) 3175.52,2146.46 3137.33,2108.27 3124.85,2108.27 3115,2098.43 3096.46,2098.43 3092.52,2102.36 3092.52,2149.48 3098.43,2155.39 3111.15,2155.39 v1(3112.2,2154.33) 3139.76,2154.33 3179.13,2193.7 v1(3212.2,2193.7) ; v1(3553.15,1244.09) 3547.24,1250 3547.24,1348.43 3657.48,1458.66 v1(3694.88,1458.66) ; v1(3594.49,1244.09) 3600.39,1250 3600.39,1334.65 3681.1,1415.35 3720.47,1415.35 v1(3722.44,1417.32) ; v1(3635.83,1244.09) 3629.92,1250 3629.92,1287.4 3718.5,1375.98 v1(3757.87,1375.98) ; v1(3677.17,1244.09) 3683.07,1250 3683.07,1271.65 3746.06,1334.65 v1(3757.87,1334.65) ; v1(4322.83,1562.99) 4322.83,1578.74 4360.24,1578.74 v1(4366.14,1572.83) ; v1(4322.83,1677.17) 4322.83,1692.91 4356.3,1692.91 v1(4362.2,1687.01) ; v1(4328.74,2917.32) 4334.65,2911.42 4366.14,2911.42 v1(4372.05,2917.32) ; v1(4330.71,2877.95) 4334.65,2881.89 4366.14,2881.89 v1(4372.05,2875.98) ; v1(4377.95,2179.13) 4372.05,2173.23 4287.4,2173.23 3726.38,1612.2 3037.4,1612.2 2728.35,1303.15 2019.68,1303.15 1860.24,1462.6 1746.06,1462.6 1746.06,1433.07 1799.21,1433.07 ; v1(4448.82,2319.69) 4421.26,2319.69 4404.72,2303.15 4251.97,2303.15 3679.13,1730.32 2990.16,1730.32 2681.1,1421.26 2106.3,1421.26 1891.73,1635.83 1226.38,1635.83 1226.38,1604.33 1891.73,1604.33 2094.49,1401.57 2688.98,1401.57 2998.03,1710.63 3687.01,1710.63 4259.84,2283.46 4419.29,2283.46 4429.13,2293.31 4484.25,2293.31 4510.63,2319.69 v1(4578.74,2319.69) ; v1(4449.21,2760.63) v1(4470.47,2760.63) ; v1(4460.63,2389.76) 4456.69,2393.7 4232.28,2393.7 3647.64,1809.06 2958.66,1809.06 2649.61,1500 2153.54,1500 1903.54,1750 720.47,1750 v1(720.47,1765.75) 720.47,1781.5 1903.54,1781.5 2165.35,1519.69 2641.73,1519.69 2950.79,1828.74 3639.76,1828.74 4224.41,2413.39 4371.26,2413.39 4372.05,2414.17 v1(4553.54,2414.17) ; v1(4578.74,2162.2) 4594.49,2177.95 4594.49,2224.41 4586.61,2232.28 4529.53,2232.28 4505.91,2208.66 4480.32,2208.66 4468.5,2196.85 4468.5,2188.98 4464.57,2185.04 4427.17,2185.04 4395.67,2153.54 4295.28,2153.54 3734.25,1592.52 3045.28,1592.52 2736.22,1283.46 1996.06,1283.46 1846.46,1433.07 1799.21,1433.07 ; v1(4578.74,2216.54) 4549.21,2216.54 4498.03,2165.35 4437.01,2165.35 4405.51,2133.86 4303.15,2133.86 3742.13,1572.83 3053.15,1572.83 2744.09,1263.78 1968.5,1263.78 1830.71,1401.57 1799.21,1401.57 1799.21,1433.07 ; v1(5055.12,3013.78) 5049.21,3007.87 5049.21,2972.44 5100.39,2972.44 v1(5100.39,3013.78) ; 1687.01,3301.18 1722.44,3301.18 ; 1722.44,3301.18 1757.87,3301.18 ; 1324.8,1525.59 1891.73,1525.59 2064.96,1352.36 2708.66,1352.36 3017.72,1661.42 3706.69,1661.42 4279.53,2234.25 4476.38,2234.25 4484.25,2242.13 v1(4484.25,2257.87) 4478.35,2263.78 4442.91,2263.78 4433.07,2253.94 4271.65,2253.94 3698.82,1681.1 3009.84,1681.1 2700.79,1372.05 2076.77,1372.05 1891.73,1557.09 1324.8,1557.09 1324.8,1525.59
  Bottom w7.87: v1(811.02,3238.19) 793.31,3220.47 789.37,3220.47 789.37,2712.6 1125.98,2375.98 2495.67,2375.98 v1(2527.17,2344.49) ; v1(820.87,3385.83) 820.87,3372.05 1009.84,3183.07 1009.84,2795.28 v1(1062.99,2742.13) 1062.99,2726.38 1118.11,2671.26 v1(1332.68,2671.26) ; v1(1007.87,2291.34) 1019.69,2273.62 1964.57,2273.62 ; 1641.73,3301.18 v1(1641.73,3181.1) 1641.73,3173.23 1726.38,3088.58 1937.01,3088.58 2053.15,2972.44 2240.16,2972.44 2269.68,3001.97 2269.68,3059.06 v1(2257.87,3070.87) ; J17.12@1975.59,2232.68 1975.59,2262.6 1964.57,2273.62 ; v1(2427.17,2167.32) 2320.87,2273.62 1964.57,2273.62 ; v1(2472.44,2933.07) 2472.44,2927.17 2488.19,2911.42 2561.02,2911.42 2574.8,2897.64 2606.3,2897.64 2718.5,2785.43 2866.14,2785.43 3003.94,2923.23 3255.91,2923.23 3468.5,3135.83 3541.34,3135.83 3608.27,3202.76 v1(3608.27,3224.41) 3608.27,3248.43 3618.11,3258.27 v1(3635.04,3258.27)
  Bottom w11.81: v1(2167.32,393.7) 2234.25,393.7 2468.5,627.95 v1(2649.61,627.95) ; v1(2187.01,464.57) 2210.63,464.57 2444.88,698.82 3324.8,698.82 3391.73,631.89 v1(3450.79,631.89) ; v1(2202.76,429.13) 2222.44,429.13 2456.69,663.39 v1(2557.09,663.39) ; v1(2472.44,2954.72) 2472.44,3000 2529.53,3057.09 3194.88,3057.09 3399.61,3261.81 v1(3399.61,3281.5)
  Bottom w15.75: v1(90.55,1687.01) 90.55,440.94 137.8,393.7 v1(181.1,393.7) ; v1(163.39,1635.83) v1(163.39,812.99) 163.39,505.91 204.72,464.57 v1(2187.01,464.57)
  other v1: 76.77,-114.17 177.17,-114.17 277.56,-114.17 377.95,-114.17 478.35,-114.17 549.21,-114.17 620.08,-114.17 690.94,-114.17 761.81,-114.17 832.68,-114.17 903.54,-114.17 974.41,-114.17 1045.28,-114.17 1116.14,-114.17 1187.01,-114.17 1257.87,-114.17 1328.74,-114.17 1399.61,-114.17 1470.47,-114.17 1541.34,-114.17 1612.2,-114.17 1683.07,-114.17 1753.94,-114.17 1824.8,-114.17 1895.67,-114.17 1966.54,-114.17 2037.4,-114.17 2108.27,-114.17 2179.13,-114.17 2391.73,-114.17 2462.6,-114.17 2533.46,-114.17 2604.33,-114.17 2675.2,-114.17 2746.06,-114.17 2816.93,-114.17 2887.8,-114.17 2958.66,-114.17 3029.53,-114.17 3100.39,-114.17 3171.26,-114.17 3242.13,-114.17 3312.99,-114.17 3383.86,-114.17 3454.72,-114.17 3525.59,-114.17 3596.46,-114.17 3667.32,-114.17 3738.19,-114.17 3809.06,-114.17 3879.92,-114.17 3950.79,-114.17 4021.65,-114.17 4092.52,-114.17 4163.39,-114.17 4234.25,-114.17 4305.12,-114.17 4375.98,-114.17 4446.85,-114.17 4517.72,-114.17 4588.58,-114.17 4659.45,-114.17 4730.32,-114.17 4801.18,-114.17 4877.95,-114.17 4954.72,-114.17 5031.5,-114.17 5108.27,-114.17 5185.04,-114.17 5261.81,-114.17 5338.58,-114.17 5415.35,-114.17 5492.13,-114.17 5568.9,-114.17 5645.67,-114.17 5722.44,-114.17 5799.21,-114.17 5875.98,-114.17 5952.76,-114.17 6029.53,-114.17 5005.91,-78.74 6082.68,-78.74 2777.56,-76.77 2992.13,-76.77 3066.93,-76.77 2494.09,-74.8 2566.93,-74.8 2637.8,-74.8 2706.69,-74.8 2850.39,-74.8 2925.2,-74.8 4354.33,-55.12 4106.3,-53.15 4175.2,-53.15 4281.5,-53.15 5061.02,-51.18 3974.41,-43.31 4507.87,-33.46 4600.39,-33.46 5576.77,-33.46 3828.74,-31.5 5740.16,-31.5 3484.25,-25.59 3728.35,-25.59 5383.86,-25.59 4929.13,-19.68 3594.49,-9.84 4098.43,-3.94 4316.93,-3.94 3342.52,5.91 4210.63,5.91 4236.22,5.91 5838.58,7.87 6135.83,11.81 3236.22,15.75 5017.72,19.69 397.64,29.53 3909.45,29.53 775.59,31.5 907.48,33.46 1066.93,35.43 1482.28,35.43 5452.76,35.43 238.19,37.4 4602.36,37.4 1283.46,39.37 4832.68,41.34 5683.07,41.34 588.58,43.31 4061.02,47.24 4124.02,47.24 4332.68,51.18 3826.77,55.12 4978.35,55.12 4724.41,61.02 3464.57,62.99 1383.86,64.96 2043.31,74.8 5375.98,78.74 6135.83,80.71 3622.05,84.65 1775.59,86.61 1909.45,86.61 5887.8,86.61 1624.02,90.55 -114.17,100.39 1295.28,100.39 120.08,104.33 4114.17,110.24 4338.58,110.24 4362.2,110.24 5748.03,116.14 4677.17,120.08 6049.21,120.08 3683.07,135.83 3917.32,135.83 4875.98,135.83 4978.35,135.83 1433.07,137.8 4775.59,139.76 5816.93,143.7 629.92,145.67 748.03,145.67 807.09,145.67 866.14,145.67 925.2,145.67 5925.2,147.64 6135.83,149.61 4614.17,151.57 74.8,157.48 1608.27,159.45 -114.17,167.32 4125.98,173.23 4342.52,173.23 1131.89,181.1 3446.85,181.1 3580.71,185.04 4978.35,185.04 4417.32,187.01 2208.66,206.69 2285.43,206.69 4045.28,208.66 5389.76,208.66 1263.78,210.63 2149.61,210.63 -45.28,214.57 13.78,216.54 6135.83,218.5 1811.02,222.44 1927.17,226.38 139.76,232.28 -114.17,234.25 4881.89,234.25 4133.86,238.19 4336.61,238.19 5045.28,240.16 3899.61,248.03 1811.02,251.97 1931.1,253.94 5994.09,259.84 1450.79,261.81 4602.36,263.78 2153.54,269.69 3994.09,269.69 629.92,271.65 2421.26,273.62 5714.57,273.62 5832.68,277.56 4728.35,281.5 1116.14,285.43 6135.83,287.4 1000,289.37 480.31,293.31 5238.19,293.31 391.73,295.28 5021.65,297.24 -114.17,301.18 5122.05,303.15 5385.83,303.15 2208.66,309.06 4206.69,311.02 4261.81,311.02 4072.83,312.99 1244.09,314.96 1379.92,314.96 4133.86,316.93 4336.61,316.93 2261.81,324.8 2153.54,332.68 3905.51,334.65 3960.63,336.61 4027.56,336.61 5525.59,340.55 4903.54,344.49 4805.12,346.46 2342.52,348.43 4732.28,348.43 214.57,350.39 336.61,350.39 722.44,350.39 777.56,350.39 895.67,350.39 5316.93,354.33 4667.32,356.3 5887.8,356.3 6051.18,356.3 6135.83,356.3 5431.1,358.27 5962.6,360.24 -114.17,368.11 5163.39,370.08 5059.06,374.02 5104.33,374.02 5736.22,375.98 5614.17,377.95 263.78,393.7 346.46,393.7 476.38,393.7 4978.35,395.67 4545.28,397.64 4574.8,397.64 4746.06,407.48 4789.37,407.48 5086.61,407.48 5125.98,407.48 5196.85,409.45 4545.28,419.29 6135.83,425.2 360.24,429.13 407.48,429.13 505.91,429.13 541.34,429.13 580.71,429.13 620.08,429.13 659.45,429.13 698.82,429.13 1608.27,429.13 1773.62,429.13 1881.89,429.13 1917.32,429.13 5312.99,429.13 777.56,431.1 2047.24,431.1 -114.17,435.04 5509.84,435.04 4679.13,438.98 4496.06,442.91 4519.68,442.91 4543.31,442.91 4860.24,448.82 4893.7,448.82 5773.62,450.79 5913.39,452.76 6061.02,454.72 5657.48,456.69 4681.1,458.66 4779.53,460.63 3728.35,476.38 3472.44,478.35 3582.68,478.35 3618.11,478.35 5399.61,478.35 5145.67,488.19 6135.83,494.09 5344.49,498.03 -114.17,501.97 5476.38,505.91 4287.4,507.87 4314.96,507.87 4340.55,507.87 4679.13,507.87 4781.5,507.87 4877.95,507.87 3277.56,511.81 3307.09,511.81 307.09,513.78 3773.62,519.69 6070.87,519.69 5704.72,527.56 5346.46,529.53 5854.33,531.5 4998.03,533.46 5043.31,533.46 5088.58,533.46 1025.59,543.31 1267.72,543.31 1407.48,543.31 385.83,545.28 4519.68,545.28 4600.39,545.28 4224.41,551.18 3600.39,555.12 3866.14,555.12 3248.03,559.06 3269.68,559.06 5425.2,559.06 5344.49,561.02 6135.83,562.99 -114.17,568.9 718.5,574.8 4998.03,576.77 5088.58,576.77 895.67,578.74 950.79,578.74 5204.72,580.71 125.98,584.65 4663.39,584.65 3488.19,594.49 1655.51,596.46 4458.66,596.46 4484.25,596.46 5151.57,596.46 1118.11,598.43 4805.12,600.39 4850.39,600.39 5425.2,600.39 4078.74,604.33 4118.11,604.33 3564.96,614.17 3637.8,614.17 3710.63,614.17 718.5,616.14 4318.9,616.14 954.72,618.11 838.58,620.08 4659.45,620.08 4998.03,624.02 5043.31,624.02 5088.58,624.02 2826.77,627.95 2944.88,627.95 3045.28,627.95 3118.11,627.95 3259.84,627.95 5801.18,629.92 3476.38,631.89 6135.83,631.89 -114.17,635.83 4419.29,635.83 3332.68,637.8 5537.4,639.76 5625.98,639.76 5425.2,641.73 4820.87,647.64 5917.32,651.57 4279.53,655.51 4736.22,659.45 2736.22,663.39 2850.39,663.39 2915.35,663.39 3805.12,667.32 4206.69,669.29 5177.17,675.2 3710.63,677.17 3730.32,677.17 4460.63,677.17 4608.27,681.1 5425.2,683.07 4248.03,687.01 3874.02,696.85 370.08,698.82 5041.34,700.79 6135.83,700.79 -114.17,702.76 125.98,702.76 5994.09,702.76 4248.03,706.69 5110.24,708.66 5870.08,708.66 4836.61,712.6 5464.57,714.57 4159.45,716.54 5687.01,720.47 5338.58,726.38 2444.88,738.19 4929.13,746.06 4206.69,750 5009.84,750 5061.02,750 4446.85,757.87 6031.5,767.72 -114.17,769.69 6135.83,769.69 4000,773.62 4659.45,773.62 4179.13,779.53 5425.2,785.43 5744.09,789.37 5921.26,791.34 4053.15,793.31 4287.4,803.15 4559.06,805.12 4374.02,809.06 125.98,820.87 5425.2,824.8 -114.17,836.61 6135.83,838.58 2509.84,852.36 4047.24,858.27 4090.55,858.27 5425.2,864.17 2582.68,874.02 5846.46,874.02 2389.76,875.98 4551.18,875.98 4476.38,877.95 5696.85,879.92 4269.68,889.76 358.27,891.73 4360.24,895.67 -114.17,903.54 6135.83,907.48 401.57,923.23 5316.93,933.07 5480.32,933.07 4040.55,953.54 4095.67,957.48 4135.04,957.48 5521.65,958.66 5757.87,966.54 5879.92,966.54 834.65,968.5 -114.17,970.47 5196.85,972.44 5389.76,974.41 6043.31,974.41 5627.95,976.38 6135.83,976.38 5521.65,992.13 3952.76,998.03 4251.97,1005.91 4328.74,1005.91 5374.02,1005.91 5316.93,1009.84 433.07,1017.72 224.41,1029.53 3437.01,1029.53 5777.56,1031.5 5864.17,1031.5 5978.35,1031.5 5659.45,1033.46 -114.17,1037.4 6135.83,1045.28 5098.43,1066.93 324.8,1070.87 265.75,1094.49 -114.17,1104.33 671.26,1112.2 4255.91,1112.2 6135.83,1114.17 4842.52,1120.08 5029.53,1120.08 2692.91,1122.05 966.54,1133.86 4192.91,1165.35 3265.75,1167.32 -114.17,1171.26 4746.06,1183.07 6135.83,1183.07 5271.65,1190.94 5452.76,1192.91 3299.21,1200.79 381.89,1202.76 3299.21,1220.47 -114.17,1238.19 1366.14,1240.16 6135.83,1251.97 332.68,1253.94 765.75,1253.94 938.98,1253.94 1179.13,1253.94 4883.86,1253.94 582.68,1263.78 5133.86,1271.65 5190.94,1271.65 5248.03,1273.62 5273.62,1273.62 1423.23,1283.46 582.68,1285.43 5133.86,1293.31 5190.94,1293.31 330.71,1295.28 393.7,1295.28 5248.03,1295.28 5273.62,1295.28 5049.21,1301.18 -114.17,1305.12 125.98,1305.12 4935.04,1314.96 1537.4,1318.9 6135.83,1320.87 1084.65,1324.8 547.24,1334.65 844.49,1342.52 354.33,1344.49 3320.87,1364.17 507.87,1366.14 -114.17,1372.05 5427.17,1381.89 5446.85,1381.89 5472.44,1383.86 5492.13,1383.86 6135.83,1389.76 5427.17,1401.57 5446.85,1401.57 4870.08,1403.54 6037.4,1409.45 5850.39,1413.39 5944.88,1413.39 1795.28,1417.32 5001.97,1419.29 978.35,1421.26 125.98,1425.2 1362.2,1431.1 5588.58,1433.07 722.44,1435.04 1188.98,1437.01 -114.17,1438.98 1740.16,1446.85 535.43,1450.79 5541.34,1450.79 6135.83,1458.66 4324.8,1460.63 5427.17,1462.6 5446.85,1462.6 5848.43,1466.54 1472.44,1470.47 5937.01,1472.44 5706.69,1474.41 3328.74,1476.38 5657.48,1501.97 -114.17,1505.91 5564.96,1507.87 5720.47,1517.72 5937.01,1527.56 6135.83,1527.56 4533.46,1529.53 1175.2,1531.5 4393.7,1531.5 5564.96,1533.46 5852.36,1535.43 1316.93,1541.34 4322.83,1541.34 125.98,1543.31 1003.94,1547.24 1062.99,1547.24 5716.54,1553.15 6023.62,1553.15 5645.67,1564.96 5503.94,1566.93 5582.68,1566.93 -114.17,1572.83 486.22,1574.8 685.04,1574.8 856.3,1574.8 5324.8,1584.65 5346.46,1584.65 5383.86,1584.65 5710.63,1594.49 6135.83,1596.46 4956.69,1602.36 5198.82,1602.36 2405.51,1604.33 2568.9,1608.27 5816.93,1608.27 5324.8,1612.2 5346.46,1612.2 4322.83,1614.17 4366.14,1614.17 1220.47,1620.08 4403.54,1622.05 5694.88,1635.83 5324.8,1637.8 5346.46,1637.8 -114.17,1639.76 6009.84,1649.61 4322.83,1655.51 307.09,1657.48 6072.83,1657.48 125.98,1661.42 6135.83,1665.35 832.68,1683.07 4551.18,1688.98 216.54,1694.88 5700.79,1696.85 2482.28,1702.76 -114.17,1706.69 586.61,1716.54 5805.12,1716.54 5887.8,1724.41 6135.83,1734.25 4330.71,1751.97 4372.05,1751.97 5129.92,1761.81 350.39,1763.78 -114.17,1773.62 5838.58,1777.56 5718.5,1787.4 2429.13,1791.34 2633.86,1791.34 543.31,1793.31 6135.83,1803.15 4984.25,1805.12 6059.06,1820.87 4553.15,1826.77 5129.92,1832.68 2549.21,1838.58 -114.17,1840.55 5948.82,1848.43 2671.26,1870.08 6135.83,1872.05 5812.99,1875.98 2435.04,1883.86 5127.95,1940.94 6135.83,1940.94 2529.53,1962.6 5129.92,1966.54 4399.61,1988.98 4421.26,1988.98 4507.87,1988.98 4529.53,1988.98 4984.25,2000 6135.83,2009.84 5161.42,2027.56 1488.19,2039.37 -114.17,2041.34 1462.6,2043.31 1049.21,2045.28 5708.66,2045.28 5730.32,2045.28 5364.17,2055.12 5391.73,2055.12 907.48,2057.09 1257.87,2066.93 5708.66,2066.93 5730.32,2066.93 2982.28,2070.87 5364.17,2078.74 5391.73,2078.74 6135.83,2078.74 2531.5,2080.71 31.5,2082.68 5431.1,2086.61 5452.76,2086.61 5476.38,2086.61 5500,2086.61 5523.62,2086.61 4488.19,2099.21 1202.76,2102.36 974.41,2104.33 885.83,2106.3 -114.17,2108.27 5431.1,2110.24 5452.76,2110.24 5476.38,2110.24 5500,2110.24 5523.62,2110.24 1064.96,2112.2 31.5,2118.11 2472.44,2120.08 1283.46,2124.02 1322.83,2124.02 1208.66,2137.8 6135.83,2147.64 2614.17,2155.51 5187.01,2157.48 5216.54,2157.48 5242.13,2159.45 3017.72,2160.24 -114.17,2175.2 5187.01,2181.1 5216.54,2181.1 5236.22,2181.1 3017.72,2181.89 4988.19,2187.01 3106.3,2193.7 1433.07,2208.66 6135.83,2216.54 1346.46,2218.5 5163.39,2218.5 5190.94,2218.5 3125.98,2222.44 2194.88,2226.38 2139.76,2228.35 2364.17,2228.35 1346.46,2240.16 -114.17,2242.13 5163.39,2248.03 5190.94,2248.03 246.06,2269.69 283.46,2269.69 375.98,2269.69 417.32,2269.69 1352.36,2269.69 5163.39,2281.5 5190.94,2281.5 6135.83,2285.43 155.51,2289.37 952.76,2291.34 984.25,2291.34 3555.12,2299.21 -114.17,2309.06 5165.35,2320.87 5190.94,2320.87 4968.5,2354.33 6135.83,2354.33 39.37,2358.27 116.14,2358.27 -114.17,2375.98 2045.28,2403.54 72.83,2405.51 1194.88,2405.51 1716.54,2407.48 6135.83,2423.23 120.08,2427.17 3677.17,2427.17 5204.72,2440.94 -114.17,2442.91 4484.25,2461.42 1204.72,2462.6 1236.22,2462.6 41.34,2464.57 1322.83,2466.54 328.74,2470.47 1389.76,2476.38 1452.76,2476.38 1683.07,2476.38 1750,2476.38 1866.14,2476.38 5135.83,2482.28 5167.32,2482.28 5196.85,2482.28 635.83,2486.22 6135.83,2492.13 1984.25,2500 2033.46,2501.97 2096.46,2501.97 5399.61,2505.91 5498.03,2505.91 4449.21,2508.66 4555.12,2508.66 5135.83,2507.87 5167.32,2507.87 5196.85,2507.87 -114.17,2509.84 980.31,2527.56 5372.05,2531.5 5399.61,2531.5 559.06,2533.46 614.17,2533.46 3468.5,2533.46 5102.36,2533.46 5135.83,2533.46 5167.32,2533.46 5196.85,2533.46 5517.72,2539.37 5541.34,2539.37 5566.93,2539.37 5600.39,2539.37 5631.89,2539.37 55.12,2543.31 151.57,2543.31 3604.33,2545.28 488.19,2549.21 4555.51,2555.91 1031.5,2557.09 1051.18,2557.09 6135.83,2561.02 391.73,2564.96 -114.17,2576.77 620.08,2586.61 1039.37,2588.58 1238.19,2590.55 1265.75,2590.55 1561.02,2590.55 1588.58,2590.55 2031.5,2590.55 2051.18,2590.55 2120.08,2590.55 2139.76,2590.55 3362.2,2592.52 261.81,2598.43 1019.69,2608.27 5598.43,2614.17 5629.92,2614.17 4935.04,2622.05 4992.13,2624.02 513.78,2627.95 5102.36,2629.92 6135.83,2629.92 1551.18,2631.89 1604.33,2631.89 2055.12,2631.89 2074.8,2631.89 2179.13,2631.89 3500,2631.89 5598.43,2635.83 5629.92,2635.83 -114.17,2643.7 5041.34,2647.64 5061.02,2647.64 643.7,2659.45 1360.24,2671.26 1389.76,2671.26 3657.48,2671.26 1281.5,2673.23 1600.39,2673.23 1629.92,2673.23 1653.54,2673.23 2090.55,2673.23 2120.08,2673.23 4921.26,2679.13 572.83,2683.07 6135.83,2698.82 409.45,2700.79 230.31,2706.69 -114.17,2710.63 5041.34,2710.63 5061.02,2710.63 31.5,2716.54 574.8,2730.32 3549.21,2736.22 3450.79,2738.19 3042.91,2760.63 3210.24,2760.63 5165.35,2759.84 5192.91,2759.84 6135.83,2767.72 523.62,2775.59 -114.17,2777.56 5165.35,2781.5 5192.91,2781.5 5224.41,2789.37 1263.78,2797.24 1175.2,2801.18 3653.54,2809.06 1767.72,2811.02 590.55,2812.99 1803.15,2812.99 1153.54,2816.93 1616.14,2816.93 37.4,2826.77 1891.73,2832.68 1940.94,2832.68 1767.72,2834.65 1803.15,2834.65 4330.71,2834.65 4372.05,2834.65 6135.83,2836.61 1742.13,2842.52 -114.17,2844.49 1537.4,2850.39 1155.51,2852.36 1641.73,2858.27 1592.52,2860.24 1706.69,2860.24 3529.53,2872.05 1875.98,2887.8 1911.42,2887.8 3407.48,2891.73 2338.58,2905.51 6135.83,2905.51 -114.17,2911.42 2586.61,2917.32 4978.35,2917.32 4846.46,2919.29 4868.11,2919.29 2698.82,2921.26 474.41,2923.23 5734.25,2925.2 3610.24,2931.1 5100.39,2933.07 5051.18,2935.04 5145.67,2935.04 4868.11,2938.98 4978.35,2938.98 27.56,2940.94 1649.61,2940.94 1677.17,2940.94 4846.46,2940.94 5700.79,2952.76 1840.55,2956.69 1862.2,2956.69 2700.79,2962.6 1677.17,2964.57 4372.05,2966.54 4326.77,2968.5 751.97,2974.41 1389.76,2974.41 6135.83,2974.41 -114.17,2978.35 2338.58,2980.32 1515.75,2990.16 6080.71,2998.03 1970.47,3000 2062.99,3000 2131.89,3000 2198.82,3000 1389.76,3001.97 2765.75,3003.94 751.97,3005.91 2543.31,3005.91 2590.55,3005.91 2637.8,3005.91 561.02,3007.87 582.68,3007.87 5149.61,3013.78 6017.72,3015.75 1515.75,3017.72 1840.55,3017.72 1864.17,3017.72 2062.99,3023.62 2133.86,3023.62 2198.82,3023.62 440.94,3025.59 5671.26,3031.5 1387.8,3033.46 5750,3037.4 1850.39,3041.34 6135.83,3043.31 -114.17,3045.28 1988.19,3051.18 2057.09,3051.18 6078.74,3053.15 29.53,3055.12 1372.05,3068.9 2171.26,3068.9 5816.93,3068.9 1210.63,3070.87 1261.81,3070.87 397.64,3072.83 2320.87,3072.83 2403.54,3078.74 5651.57,3080.71 1793.31,3084.65 1643.7,3090.55 5757.87,3090.55 5696.85,3094.49 131.89,3100.39 6017.72,3106.3 1421.26,3108.27 2232.28,3108.27 1474.41,3110.24 2537.4,3110.24 -114.17,3112.2 6135.83,3112.2 1210.63,3114.17 1261.81,3114.17 2478.35,3114.17 2291.34,3120.08 2326.77,3120.08 2828.74,3125.98 261.81,3127.95 2968.5,3127.95 1368.11,3129.92 2112.2,3133.86 5687.01,3143.7 5751.97,3143.7 6074.8,3143.7 5789.37,3145.67 1210.63,3151.57 1261.81,3151.57 2157.48,3167.32 2783.46,3175.2 2946.85,3175.2 -114.17,3179.13 6135.83,3181.1 281.5,3188.98 118.11,3192.91 2698.82,3196.85 5100.39,3196.85 4988.19,3198.82 2870.08,3200.79 4874.02,3206.69 5255.91,3206.69 6080.71,3210.63 5379.92,3220.47 2712.6,3226.38 5458.66,3230.32 5606.3,3230.32 5533.46,3232.28 -114.17,3246.06 2789.37,3250 6135.83,3250 1962.6,3253.94 2946.85,3253.94 6066.93,3267.72 1112.2,3269.69 214.57,3279.53 1342.52,3279.53 1167.32,3281.5 1224.41,3281.5 1277.56,3281.5 1395.67,3293.31 1962.6,3293.31 5529.53,3295.28 4204.72,3297.24 5472.44,3297.24 5990.16,3297.24 6122.05,3309.06 2421.26,3318.9 -78.74,3328.74 0,3383.86 92.52,3383.86 185.04,3383.86 277.56,3383.86 370.08,3383.86 462.6,3383.86 1202.76,3383.86 1295.28,3383.86 1480.32,3383.86 2127.95,3383.86 2220.47,3383.86 2312.99,3383.86 2405.51,3383.86 2498.03,3383.86 2590.55,3383.86 2775.59,3383.86 2868.11,3383.86 2960.63,3383.86 3053.15,3383.86 3145.67,3383.86 3238.19,3383.86 3330.71,3383.86 3423.23,3383.86 3515.75,3383.86 3608.27,3383.86 3885.83,3383.86 4070.87,3383.86 4163.39,3383.86 4255.91,3383.86 4348.43,3383.86 4440.94,3383.86 4533.46,3383.86 4625.98,3383.86 4718.5,3383.86
GPIO0_A2_1V8: P24.1 U33.64 | length 118.3
  Top w3.94: v1(4382.28,2492.91) U33.64@4415.35,2492.91
  Bottom w3.94: P24.1@4312.99,2531.5 4338.58,2505.91 4369.29,2505.91 v1(4382.28,2492.91)
GPIO0_A5_1V8: P25.1 U33.68 | length 61
  Top w3.94: v1(4382.28,2524.41) U33.68@4415.35,2524.41
  Bottom w3.94: v1(4382.28,2524.41) 4400.79,2524.41 P25.1@4407.48,2517.72
GPIO1_C1: J11.31 U33.30 | length 3531.8
  Top w3.94: J11.31@1693.7,1877.56 1693.7,1511.02 v1(1710.63,1494.09) ; v1(4342.52,2214.57) 4366.14,2214.57 4376.77,2225.2 U33.30@4415.35,2225.2
  Bottom w3.94: v1(1710.63,1494.09) 1891.73,1494.09 2053.15,1332.68 2716.54,1332.68 3025.59,1641.73 3714.57,1641.73 4275.59,2202.76 4330.71,2202.76 v1(4342.52,2214.57)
